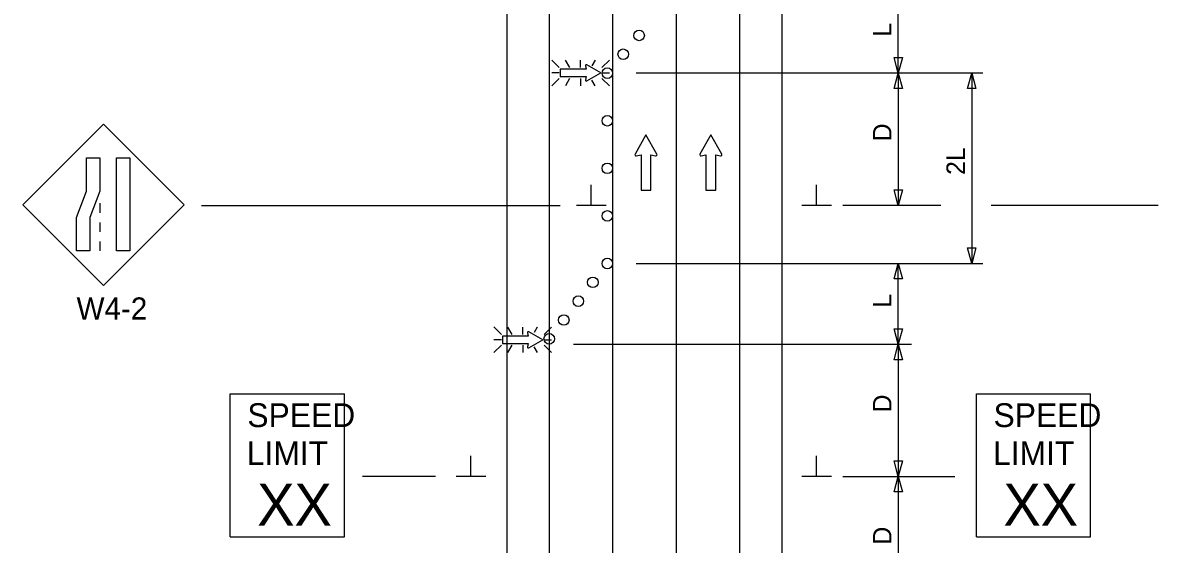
# Model space of a CAD drawing. Extents: x 16576 to 19508, y 5728 to 6974.
# Drawn here: x 17762.5 to 18192, y 6468 to 6665.3 of the extents above; entities that cross this region are included whole.
import ezdxf

# ---------------------------------------------------------------- set-up
doc = ezdxf.new("R2010")
doc.units = 0
for name, color, linetype in [('ALI_LEGAL_EX', 7, 'Continuous'), ('MT_SCRATCH_LEVEL_E', 7, 'Continuous'), ('PAVT_EDGE_EX', 7, 'Continuous'), ('TRAFFIC_SIGNS_PR', 7, 'Continuous'), ('TYPICAL_TEXT_DIMEN_PR', 7, 'Continuous')]:
    doc.layers.add(name, color=color, linetype=linetype)

msp = doc.modelspace()

# ---------------------------------------------------------------- linework, layer by layer
at = {"layer": 'ALI_LEGAL_EX'}
for p, q in [((17985.63, 6921.33), (17985.63, 6077.19)), ((18009.63, 6921.33), (18009.63, 6077.19))]:
    msp.add_line(p, q, dxfattribs=at)
for points in [[(17985.63, 6621.33), (17985.63, 6596.33)], [(18009.63, 6621.33), (18009.63, 6596.33)], [(17985.63, 6521.33), (17985.63, 6496.33)], [(18009.63, 6521.33), (18009.63, 6496.33)]]:
    msp.add_lwpolyline(points, dxfattribs=at)
at = {"layer": 'MT_SCRATCH_LEVEL_E'}
for p, q in [((17998.21, 6622.84), (17994.1, 6615.6)), ((18002.35, 6615.6), (17998.21, 6622.84)), ((18022.77, 6622.84), (18018.65, 6615.6)), ((18026.91, 6615.6), (18022.77, 6622.84)), ((17994.58, 6614.92), (17996.35, 6615.24)), ((17996.35, 6615.24), (17996.35, 6601.98)), ((18000.1, 6601.98), (18000.1, 6615.24)), ((18000.1, 6615.24), (18001.87, 6614.92)), ((18019.14, 6614.92), (18020.91, 6615.24)), ((18020.91, 6615.24), (18020.91, 6601.98)), ((18024.66, 6601.98), (18024.66, 6615.24)), ((18024.66, 6615.24), (18026.43, 6614.92)), ((17996.35, 6601.98), (18000.1, 6601.98)), ((18020.91, 6601.98), (18024.66, 6601.98))]:
    msp.add_line(p, q, dxfattribs=at)
for centre, start, end in [((17994.5, 6615.38), 150.4248, 279.9638), ((18001.94, 6615.38), 260.0362, 29.7731), ((18019.06, 6615.38), 150.4248, 279.9638), ((18026.5, 6615.38), 260.0362, 29.7731)]:
    msp.add_arc(centre, 0.463, start, end, dxfattribs=at)
at = {"layer": 'PAVT_EDGE_EX'}
for p, q in [((17945.63, 6921.33), (17945.63, 5988.51)), ((17961.63, 6921.33), (17961.63, 5988.51)), ((18033.63, 6921.33), (18033.63, 5988.51)), ((18049.63, 6921.33), (18049.63, 5988.51))]:
    msp.add_line(p, q, dxfattribs=at)
at = {"layer": 'TRAFFIC_SIGNS_PR'}
for p, q in [((17965.41, 6648.3), (17962.59, 6651.12)), ((17967.71, 6651.12), (17969.33, 6648.3)), ((17973.49, 6648.3), (17973.49, 6651.12)), ((17978.96, 6651.12), (17977.76, 6649.02)), ((17984.4, 6651.11), (17981.58, 6648.3)), ((17965.41, 6646.27), (17962.59, 6646.27)), ((17981.58, 6646.27), (17984.4, 6646.27)), ((17965.41, 6644.23), (17962.59, 6641.41)), ((17969.36, 6644.23), (17967.73, 6641.41)), ((17973.49, 6644.23), (17973.49, 6641.41)), ((17977.68, 6643.6), (17978.94, 6641.41)), ((17984.4, 6641.41), (17981.58, 6644.23)), ((17793.03, 6626.95), (17762.48, 6596.4)), ((17823.57, 6596.4), (17793.03, 6626.95)), ((17762.48, 6596.4), (17793.03, 6565.85)), ((17791.62, 6596.95), (17791.62, 6593.35)), ((17793.03, 6565.85), (17823.57, 6596.4)), ((17791.62, 6589.75), (17791.62, 6586.15)), ((17791.62, 6582.55), (17791.62, 6578.95)), ((17943.54, 6547.35), (17940.72, 6550.17)), ((17945.83, 6550.16), (17947.46, 6547.35)), ((17951.62, 6547.35), (17951.62, 6550.16)), ((17957.09, 6550.16), (17955.88, 6548.07)), ((17962.53, 6550.16), (17959.71, 6547.35)), ((17943.54, 6545.31), (17940.72, 6545.31)), ((17943.54, 6543.28), (17940.72, 6540.46)), ((17947.49, 6543.28), (17945.86, 6540.46)), ((17951.62, 6543.28), (17951.62, 6540.46)), ((17955.8, 6542.65), (17957.06, 6540.46)), ((17959.71, 6545.31), (17962.53, 6545.31)), ((17962.53, 6540.46), (17959.71, 6543.28)), ((17840.96, 6524.84), (17884.16, 6524.84)), ((17840.96, 6470.84), (17840.96, 6524.84)), ((17884.16, 6470.84), (17884.16, 6524.84)), ((18123.2, 6524.84), (18166.4, 6524.84)), ((18123.2, 6470.84), (18123.2, 6524.84)), ((18166.4, 6470.84), (18166.4, 6524.84)), ((17840.96, 6470.84), (17884.16, 6470.84)), ((18123.2, 6470.84), (18166.4, 6470.84))]:
    msp.add_line(p, q, dxfattribs=at)
for points in [[(17975.82, 6643.25), (17981.13, 6646.27), (17975.82, 6649.31)], [(17975.32, 6648.95), (17975.55, 6647.65), (17965.83, 6647.65), (17965.83, 6644.91), (17975.55, 6644.91), (17975.32, 6643.6)], [(17953.45, 6547.99), (17953.68, 6546.7), (17943.96, 6546.7), (17943.96, 6543.95), (17953.68, 6543.95), (17953.45, 6542.65)], [(17953.95, 6542.3), (17959.26, 6545.31), (17953.95, 6548.35)]]:
    msp.add_lwpolyline(points, dxfattribs=at)
for points in [[(17791.62, 6614.1), (17791.62, 6601.52), (17787.86, 6591.53), (17787.86, 6578.95), (17782.81, 6578.95), (17782.81, 6591.53), (17786.57, 6601.52), (17786.57, 6614.1)], [(17803.03, 6614.1), (17803.03, 6578.95), (17797.97, 6578.95), (17797.97, 6614.1)]]:
    msp.add_lwpolyline(points, close=True, dxfattribs=at)
for centre in [(17995.63, 6660.48), (17989.63, 6653.34), (17983.63, 6646.2), (17983.63, 6628.19), (17983.63, 6610.19), (17983.63, 6592.19), (17983.63, 6574.19), (17978.14, 6567.06), (17972.64, 6559.94), (17967.14, 6552.81), (17961.64, 6545.68)]:
    msp.add_circle(centre, 2, dxfattribs=at)
for centre, start, end in [((17975.66, 6649.01), 61.4833, 189.9593), ((17975.66, 6643.55), 170.7308, 298.8916), ((17953.78, 6548.05), 61.4833, 189.9593), ((17953.78, 6542.6), 170.7308, 298.8916)]:
    msp.add_arc(centre, 0.341, start, end, dxfattribs=at)
at = {"layer": 'TYPICAL_TEXT_DIMEN_PR'}
for p, q in [((18093.63, 6646.19), (18093.63, 6676.76)), ((18093.63, 6646.19), (18092.06, 6652.06)), ((18092.06, 6652.06), (18093.63, 6652.06)), ((18093.63, 6652.06), (18095.2, 6652.06)), ((18095.2, 6652.06), (18093.63, 6646.19)), ((18125.68, 6646.19), (17994.53, 6646.19)), ((18092.06, 6640.33), (18093.63, 6646.19)), ((18093.63, 6646.19), (18093.63, 6596.19)), ((18093.63, 6646.19), (18095.2, 6640.33)), ((18119.87, 6640.33), (18121.44, 6646.19)), ((18121.44, 6646.19), (18123.01, 6640.33)), ((18121.44, 6646.19), (18121.44, 6574.19)), ((18093.63, 6640.33), (18092.06, 6640.33)), ((18095.2, 6640.33), (18093.63, 6640.33)), ((18121.44, 6640.33), (18119.87, 6640.33)), ((18123.01, 6640.33), (18121.44, 6640.33)), ((17977.56, 6596.19), (17977.56, 6603.98)), ((18062.76, 6596.19), (18062.76, 6603.98)), ((18093.63, 6596.19), (18092.06, 6602.06)), ((18092.06, 6602.06), (18093.63, 6602.06)), ((18093.63, 6602.06), (18095.2, 6602.06)), ((18095.2, 6602.06), (18093.63, 6596.19)), ((18121.44, 6601.06), (18121.44, 6597.3)), ((17830.05, 6596.19), (17965.83, 6596.19)), ((17983.19, 6596.19), (17971.94, 6596.19)), ((18068.38, 6596.19), (18057.13, 6596.19)), ((18109.77, 6596.19), (18072.63, 6596.19)), ((18192.01, 6596.19), (18128.83, 6596.19)), ((18121.44, 6574.19), (18119.87, 6580.06)), ((18119.87, 6580.06), (18121.44, 6580.06)), ((18121.44, 6580.06), (18123.01, 6580.06)), ((18123.01, 6580.06), (18121.44, 6574.19)), ((17994.53, 6574.19), (18125.68, 6574.19)), ((18092.06, 6568.33), (18093.63, 6574.19)), ((18093.63, 6543.63), (18093.63, 6574.19)), ((18093.63, 6574.19), (18095.2, 6568.33)), ((18093.63, 6568.33), (18092.06, 6568.33)), ((18095.2, 6568.33), (18093.63, 6568.33)), ((18093.63, 6543.63), (18092.06, 6549.49)), ((18092.06, 6549.49), (18093.63, 6549.49)), ((18093.63, 6549.49), (18095.2, 6549.49)), ((18095.2, 6549.49), (18093.63, 6543.63)), ((17970.8, 6543.63), (18098.63, 6543.63)), ((18092.06, 6537.77), (18093.63, 6543.63)), ((18093.63, 6543.63), (18093.63, 6493.63)), ((18093.63, 6543.63), (18095.2, 6537.77)), ((18093.63, 6537.77), (18092.06, 6537.77)), ((18095.2, 6537.77), (18093.63, 6537.77)), ((17932.02, 6493.63), (17932.02, 6501.41)), ((18062.76, 6493.63), (18062.76, 6501.41)), ((18093.63, 6493.63), (18092.06, 6499.49)), ((18092.06, 6499.49), (18093.63, 6499.49)), ((18093.63, 6499.49), (18095.2, 6499.49)), ((18095.2, 6499.49), (18093.63, 6493.63)), ((17918.58, 6493.63), (17890.99, 6493.63)), ((17937.64, 6493.63), (17926.39, 6493.63)), ((18068.38, 6493.63), (18057.13, 6493.63)), ((18072.63, 6493.63), (18115.11, 6493.63)), ((18092.06, 6487.77), (18093.63, 6493.63)), ((18093.63, 6493.63), (18093.63, 6443.63)), ((18093.63, 6493.63), (18095.2, 6487.77)), ((18093.63, 6487.77), (18092.06, 6487.77)), ((18095.2, 6487.77), (18093.63, 6487.77))]:
    msp.add_line(p, q, dxfattribs=at)

# ---------------------------------------------------------------- texts
at = {"layer": 'TRAFFIC_SIGNS_PR'}
for s, height, p in [('W4-2', 8.37, (17782.85, 6552.98)), ('SPEED', 9, (17847.45, 6512.31)), ('SPEED', 9, (18129.69, 6512.31)), ('LIMIT', 9, (17847.26, 6497.91)), ('LIMIT', 9, (18129.51, 6497.91)), ('XX', 15.785, (17851.21, 6475.06)), ('XX', 15.785, (18133.45, 6475.06))]:
    msp.add_text(s, height=height, dxfattribs=at).set_placement(p)
at = {"layer": 'TYPICAL_TEXT_DIMEN_PR'}
for s, p in [('L', (18091.08, 6660.05)), ('D', (18091.08, 6620.41)), ('2L', (18118.88, 6607.7)), ('L', (18091.08, 6557.49)), ('D', (18091.08, 6517.85)), ('D', (18091.08, 6467.85))]:
    msp.add_text(s, height=7, rotation=90, dxfattribs=at).set_placement(p)

doc.saveas('drawing.dxf')
